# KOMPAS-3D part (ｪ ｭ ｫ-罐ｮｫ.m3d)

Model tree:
1. Эскиз:1
2. Операция выдавливания:1
     Расстояние 1 = 1
3. Эскиз:2
4. Операция выдавливания:2
     Расстояние 1 = 2
5. Эскиз:3
6. Вырезать элемент выдавливания:1
     Расстояние 1 = 200
7. Эскиз:4
8. Операция выдавливания:3
     Расстояние 1 = 5
9. Эскиз:5
10. Операция выдавливания:4
     Расстояние 1 = 1
11. Эскиз:6
12. Операция выдавливания:5
     Расстояние 1 = 9
13. Эскиз:7
14. Операция выдавливания:6
     Расстояние 1 = 9; Расстояние 2 = 200
15. Эскиз:8
16. Вырезать элемент выдавливания:2
     Расстояние 1 = 10
